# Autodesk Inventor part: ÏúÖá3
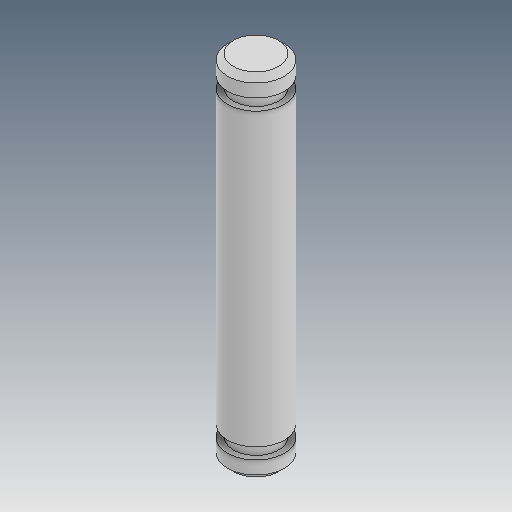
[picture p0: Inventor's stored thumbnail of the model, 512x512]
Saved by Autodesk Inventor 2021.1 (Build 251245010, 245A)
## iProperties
Created: 2015-08
Part Number: ÏúÖá3
Material: Ogólny
Document SubType Name: Modeling
Designer: user
Density: 1 g/cm^3
Appearance: Domyślna
Author: user
Revision Number: ÈÎºÎ
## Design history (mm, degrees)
feature "Ðý×ª1"
node "Bryła1"
